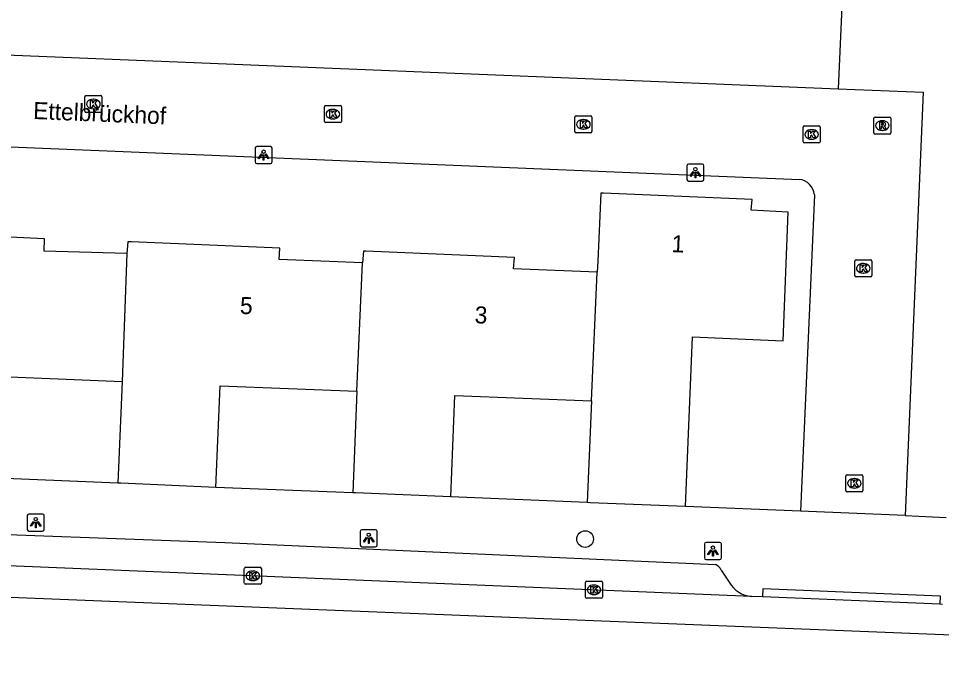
# Model space of a CAD drawing. Extents: x 160787 to 161428, y 386828 to 387483.
# Drawn here: x 161180.7 to 161234.9, y 386896.4 to 386934.4 of the extents above; entities that cross this region are included whole.
import ezdxf

# ---------------------------------------------------------------- set-up
doc = ezdxf.new("R2010")
doc.units = 0
for name, color, linetype in [('IMGEO_Boom', 7, 'Continuous'), ('IMGEO_Kolk', 7, 'Continuous'), ('IMGEO_Lichtpunt', 7, 'Continuous'), ('IMGEO_Openbare_ruimte_label', 7, 'Continuous'), ('IMGEO_Pand', 7, 'Continuous'), ('IMGEO_Pand_nummerreeks', 7, 'Continuous'), ('IMGEO_Rijbaan_lokaal_gesloten', 7, 'Continuous'), ('IMGEO_Rioolput', 7, 'Continuous'), ('IMGEO_Voetpad_open', 7, 'Continuous')]:
    doc.layers.add(name, color=color, linetype=linetype)

msp = doc.modelspace()

# ---------------------------------------------------------------- linework, layer by layer
at = {"layer": 'IMGEO_Boom'}
msp.add_circle((161213.924, 386903.837), 0.489, dxfattribs=at)
at = {"layer": 'IMGEO_Kolk'}
for p, q in [((161184.551, 386928.95), (161184.551, 386929.802)), ((161184.626, 386929.876), (161185.478, 386929.876)), ((161185.039, 386929.656), (161185.064, 386929.656)), ((161185.552, 386929.802), (161185.552, 386928.95)), ((161185.478, 386928.876), (161184.626, 386928.876)), ((161185.062, 386929.096), (161185.037, 386929.096)), ((161198.613, 386928.36), (161198.613, 386929.212)), ((161198.688, 386929.286), (161199.54, 386929.286)), ((161199.101, 386929.066), (161199.126, 386929.066)), ((161199.614, 386929.212), (161199.614, 386928.36)), ((161199.124, 386928.506), (161199.099, 386928.506)), ((161213.321, 386927.757), (161213.321, 386928.609)), ((161213.396, 386928.683), (161214.248, 386928.683)), ((161213.809, 386928.463), (161213.834, 386928.463)), ((161214.322, 386928.609), (161214.322, 386927.757)), ((161199.54, 386928.286), (161198.688, 386928.286)), ((161213.832, 386927.903), (161213.807, 386927.903)), ((161226.721, 386927.167), (161226.721, 386928.019)), ((161226.796, 386928.093), (161227.648, 386928.093)), ((161227.209, 386927.873), (161227.234, 386927.873)), ((161227.722, 386928.019), (161227.722, 386927.167)), ((161214.248, 386927.683), (161213.396, 386927.683)), ((161227.232, 386927.313), (161227.207, 386927.313)), ((161227.648, 386927.093), (161226.796, 386927.093)), ((161229.829, 386920.236), (161230.681, 386920.236)), ((161229.754, 386919.31), (161229.754, 386920.162)), ((161230.242, 386920.016), (161230.267, 386920.016)), ((161230.755, 386920.162), (161230.755, 386919.31)), ((161230.681, 386919.236), (161229.829, 386919.236)), ((161230.265, 386919.456), (161230.24, 386919.456)), ((161229.23, 386906.685), (161229.23, 386907.537)), ((161229.305, 386907.611), (161230.157, 386907.611)), ((161229.718, 386907.391), (161229.743, 386907.391)), ((161230.231, 386907.537), (161230.231, 386906.685)), ((161229.741, 386906.831), (161229.716, 386906.831)), ((161230.157, 386906.611), (161229.305, 386906.611)), ((161193.912, 386901.255), (161193.912, 386902.107)), ((161193.987, 386902.181), (161194.839, 386902.181)), ((161194.4, 386901.961), (161194.425, 386901.961)), ((161194.913, 386902.107), (161194.913, 386901.255)), ((161194.423, 386901.401), (161194.398, 386901.401)), ((161213.944, 386900.433), (161213.944, 386901.285)), ((161214.019, 386901.359), (161214.871, 386901.359)), ((161214.945, 386901.285), (161214.945, 386900.433)), ((161194.839, 386901.181), (161193.987, 386901.181)), ((161214.432, 386901.139), (161214.457, 386901.139)), ((161214.871, 386900.359), (161214.019, 386900.359)), ((161214.455, 386900.579), (161214.43, 386900.579))]:
    msp.add_line(p, q, dxfattribs=at)
for points in [[(161184.551, 386928.95), (161184.551, 386929.802)], [(161184.626, 386929.876), (161185.478, 386929.876)], [(161184.872, 386929.576), (161184.995, 386929.576), (161184.995, 386929.425), (161185.125, 386929.576), (161185.289, 386929.576), (161185.143, 386929.425), (161185.296, 386929.176), (161185.144, 386929.176), (161185.059, 386929.34), (161184.995, 386929.273), (161184.995, 386929.176), (161184.872, 386929.176), (161184.872, 386929.576)], [(161185.552, 386929.802), (161185.552, 386928.95)], [(161185.478, 386928.876), (161184.626, 386928.876)], [(161198.613, 386928.36), (161198.613, 386929.212)], [(161198.688, 386929.286), (161199.54, 386929.286)], [(161198.934, 386928.986), (161199.057, 386928.986), (161199.057, 386928.835), (161199.187, 386928.986), (161199.351, 386928.986), (161199.205, 386928.835), (161199.358, 386928.586), (161199.206, 386928.586), (161199.121, 386928.75), (161199.057, 386928.683), (161199.057, 386928.586), (161198.934, 386928.586), (161198.934, 386928.986)], [(161199.614, 386929.212), (161199.614, 386928.36)], [(161213.321, 386927.757), (161213.321, 386928.609)], [(161213.396, 386928.683), (161214.248, 386928.683)], [(161213.642, 386928.383), (161213.765, 386928.383), (161213.765, 386928.232), (161213.895, 386928.383), (161214.059, 386928.383), (161213.913, 386928.232), (161214.066, 386927.983), (161213.914, 386927.983), (161213.829, 386928.147), (161213.765, 386928.08), (161213.765, 386927.983), (161213.642, 386927.983), (161213.642, 386928.383)], [(161214.322, 386928.609), (161214.322, 386927.757)], [(161199.54, 386928.286), (161198.688, 386928.286)], [(161226.721, 386927.167), (161226.721, 386928.019)], [(161226.796, 386928.093), (161227.648, 386928.093)], [(161227.042, 386927.793), (161227.165, 386927.793), (161227.165, 386927.642), (161227.295, 386927.793), (161227.459, 386927.793), (161227.313, 386927.642), (161227.466, 386927.393), (161227.314, 386927.393), (161227.229, 386927.557), (161227.165, 386927.49), (161227.165, 386927.393), (161227.042, 386927.393), (161227.042, 386927.793)], [(161227.722, 386928.019), (161227.722, 386927.167)], [(161214.248, 386927.683), (161213.396, 386927.683)], [(161227.648, 386927.093), (161226.796, 386927.093)], [(161229.829, 386920.236), (161230.681, 386920.236)], [(161229.754, 386919.31), (161229.754, 386920.162)], [(161230.075, 386919.936), (161230.198, 386919.936), (161230.198, 386919.785), (161230.328, 386919.936), (161230.492, 386919.936), (161230.346, 386919.785), (161230.499, 386919.536), (161230.347, 386919.536), (161230.262, 386919.7), (161230.198, 386919.633), (161230.198, 386919.536), (161230.075, 386919.536), (161230.075, 386919.936)], [(161230.755, 386920.162), (161230.755, 386919.31)], [(161230.681, 386919.236), (161229.829, 386919.236)], [(161229.23, 386906.685), (161229.23, 386907.537)], [(161229.305, 386907.611), (161230.157, 386907.611)], [(161229.551, 386907.311), (161229.674, 386907.311), (161229.674, 386907.16), (161229.804, 386907.311), (161229.968, 386907.311), (161229.822, 386907.16), (161229.975, 386906.911), (161229.823, 386906.911), (161229.738, 386907.075), (161229.674, 386907.008), (161229.674, 386906.911), (161229.551, 386906.911), (161229.551, 386907.311)], [(161230.231, 386907.537), (161230.231, 386906.685)], [(161230.157, 386906.611), (161229.305, 386906.611)], [(161193.912, 386901.255), (161193.912, 386902.107)], [(161193.987, 386902.181), (161194.839, 386902.181)], [(161194.233, 386901.881), (161194.356, 386901.881), (161194.356, 386901.73), (161194.486, 386901.881), (161194.65, 386901.881), (161194.504, 386901.73), (161194.657, 386901.481), (161194.505, 386901.481), (161194.42, 386901.645), (161194.356, 386901.578), (161194.356, 386901.481), (161194.233, 386901.481), (161194.233, 386901.881)], [(161194.913, 386902.107), (161194.913, 386901.255)], [(161213.944, 386900.433), (161213.944, 386901.285)], [(161214.019, 386901.359), (161214.871, 386901.359)], [(161214.945, 386901.285), (161214.945, 386900.433)], [(161194.839, 386901.181), (161193.987, 386901.181)], [(161214.265, 386901.059), (161214.388, 386901.059), (161214.388, 386900.908), (161214.518, 386901.059), (161214.682, 386901.059), (161214.536, 386900.908), (161214.689, 386900.659), (161214.537, 386900.659), (161214.452, 386900.823), (161214.388, 386900.756), (161214.388, 386900.659), (161214.265, 386900.659), (161214.265, 386901.059)], [(161214.871, 386900.359), (161214.019, 386900.359)]]:
    msp.add_lwpolyline(points, dxfattribs=at)
for centre, start, end in [((161184.628, 386929.8), 91.552, 178.448), ((161184.628, 386929.8), 91.552, 178.448), ((161185.476, 386929.8), 1.552, 88.448), ((161185.476, 386929.8), 1.552, 88.448), ((161184.628, 386928.952), 181.552, 268.448), ((161184.628, 386928.952), 181.552, 268.448), ((161185.476, 386928.952), 271.552, 358.448), ((161185.476, 386928.952), 271.552, 358.448), ((161198.69, 386929.21), 91.552, 178.448), ((161198.69, 386929.21), 91.552, 178.448), ((161199.538, 386929.21), 1.552, 88.448), ((161199.538, 386929.21), 1.552, 88.448), ((161198.69, 386928.362), 181.552, 268.448), ((161198.69, 386928.362), 181.552, 268.448), ((161199.538, 386928.362), 271.552, 358.448), ((161199.538, 386928.362), 271.552, 358.448), ((161213.398, 386928.607), 91.552, 178.448), ((161213.398, 386928.607), 91.552, 178.448), ((161214.246, 386928.607), 1.552, 88.448), ((161214.246, 386928.607), 1.552, 88.448), ((161226.798, 386928.017), 91.552, 178.448), ((161226.798, 386928.017), 91.552, 178.448), ((161227.646, 386928.017), 1.552, 88.448), ((161227.646, 386928.017), 1.552, 88.448), ((161213.398, 386927.759), 181.552, 268.448), ((161213.398, 386927.759), 181.552, 268.448), ((161214.246, 386927.759), 271.552, 358.448), ((161214.246, 386927.759), 271.552, 358.448), ((161226.798, 386927.169), 181.552, 268.448), ((161226.798, 386927.169), 181.552, 268.448), ((161227.646, 386927.169), 271.552, 358.448), ((161227.646, 386927.169), 271.552, 358.448), ((161229.831, 386920.16), 91.552, 178.448), ((161229.831, 386920.16), 91.552, 178.448), ((161230.679, 386920.16), 1.552, 88.448), ((161230.679, 386920.16), 1.552, 88.448), ((161229.831, 386919.312), 181.552, 268.448), ((161229.831, 386919.312), 181.552, 268.448), ((161230.679, 386919.312), 271.552, 358.448), ((161230.679, 386919.312), 271.552, 358.448), ((161229.307, 386907.535), 91.552, 178.448), ((161229.307, 386907.535), 91.552, 178.448), ((161230.155, 386907.535), 1.552, 88.448), ((161230.155, 386907.535), 1.552, 88.448), ((161229.307, 386906.687), 181.552, 268.448), ((161229.307, 386906.687), 181.552, 268.448), ((161230.155, 386906.687), 271.552, 358.448), ((161230.155, 386906.687), 271.552, 358.448), ((161193.989, 386902.105), 91.552, 178.448), ((161193.989, 386902.105), 91.552, 178.448), ((161194.837, 386902.105), 1.552, 88.448), ((161194.837, 386902.105), 1.552, 88.448), ((161193.989, 386901.257), 181.552, 268.448), ((161193.989, 386901.257), 181.552, 268.448), ((161194.837, 386901.257), 271.552, 358.448), ((161194.837, 386901.257), 271.552, 358.448), ((161214.021, 386901.283), 91.552, 178.448), ((161214.021, 386901.283), 91.552, 178.448), ((161214.869, 386901.283), 1.552, 88.448), ((161214.869, 386901.283), 1.552, 88.448), ((161214.021, 386900.435), 181.552, 268.448), ((161214.021, 386900.435), 181.552, 268.448), ((161214.869, 386900.435), 271.552, 358.448), ((161214.869, 386900.435), 271.552, 358.448)]:
    msp.add_arc(centre, 0.0765, start, end, dxfattribs=at)
for centre, major_axis, ratio, start_param, end_param in [((161185.038, 386929.376), (-0.387, 0.002), 0.722429, 4.712389, 7.853982), ((161185.063, 386929.376), (-0.39, 0.002), 0.717154, 1.570796, 4.712389), ((161199.1, 386928.786), (-0.387, 0.002), 0.722429, 4.712389, 7.853982), ((161199.125, 386928.786), (-0.39, 0.002), 0.717154, 1.570796, 4.712389), ((161213.808, 386928.183), (-0.387, 0.002), 0.722429, 4.712389, 7.853982), ((161213.833, 386928.183), (-0.39, 0.002), 0.717154, 1.570796, 4.712389), ((161227.208, 386927.593), (-0.387, 0.002), 0.722429, 4.712389, 7.853982), ((161227.233, 386927.593), (-0.39, 0.002), 0.717154, 1.570796, 4.712389), ((161230.241, 386919.736), (-0.387, 0.002), 0.722429, 4.712389, 7.853982), ((161230.266, 386919.736), (-0.39, 0.002), 0.717154, 1.570796, 4.712389), ((161229.717, 386907.111), (-0.387, 0.002), 0.722429, 4.712389, 7.853982), ((161229.742, 386907.111), (-0.39, 0.002), 0.717154, 1.570796, 4.712389), ((161194.399, 386901.681), (-0.387, 0.002), 0.722429, 4.712389, 7.853982), ((161194.424, 386901.681), (-0.39, 0.002), 0.717154, 1.570796, 4.712389), ((161214.431, 386900.859), (-0.387, 0.002), 0.722429, 4.712389, 7.853982), ((161214.456, 386900.859), (-0.39, 0.002), 0.717154, 1.570796, 4.712389)]:
    msp.add_ellipse(centre, major_axis=major_axis, ratio=ratio, start_param=start_param, end_param=end_param, dxfattribs=at)
at = {"layer": 'IMGEO_Lichtpunt'}
for p, q in [((161194.543, 386926.783), (161194.543, 386925.976)), ((161194.543, 386926.783), (161194.543, 386925.976)), ((161195.445, 386926.878), (161194.637, 386926.878)), ((161195.445, 386926.878), (161194.637, 386926.878)), ((161195.539, 386925.976), (161195.539, 386926.783)), ((161195.539, 386925.976), (161195.539, 386926.783)), ((161194.637, 386925.882), (161195.445, 386925.882)), ((161194.637, 386925.882), (161195.445, 386925.882)), ((161219.9, 386925.757), (161219.9, 386924.95)), ((161219.9, 386925.757), (161219.9, 386924.95)), ((161220.802, 386925.852), (161219.994, 386925.852)), ((161220.802, 386925.852), (161219.994, 386925.852)), ((161220.896, 386924.95), (161220.896, 386925.757)), ((161220.896, 386924.95), (161220.896, 386925.757)), ((161219.994, 386924.856), (161220.802, 386924.856)), ((161219.994, 386924.856), (161220.802, 386924.856)), ((161181.167, 386905.212), (161181.167, 386904.405)), ((161181.167, 386905.212), (161181.167, 386904.405)), ((161182.069, 386905.307), (161181.261, 386905.307)), ((161182.069, 386905.307), (161181.261, 386905.307)), ((161182.163, 386904.405), (161182.163, 386905.212)), ((161182.163, 386904.405), (161182.163, 386905.212)), ((161181.261, 386904.311), (161182.069, 386904.311)), ((161181.261, 386904.311), (161182.069, 386904.311)), ((161200.719, 386904.291), (161200.719, 386903.484)), ((161200.719, 386904.291), (161200.719, 386903.484)), ((161201.621, 386904.386), (161200.813, 386904.386)), ((161201.621, 386904.386), (161200.813, 386904.386)), ((161201.715, 386903.484), (161201.715, 386904.291)), ((161201.715, 386903.484), (161201.715, 386904.291)), ((161220.93, 386903.54), (161220.93, 386902.733)), ((161220.93, 386903.54), (161220.93, 386902.733)), ((161221.832, 386903.635), (161221.024, 386903.635)), ((161221.832, 386903.635), (161221.024, 386903.635)), ((161221.926, 386902.733), (161221.926, 386903.54)), ((161221.926, 386902.733), (161221.926, 386903.54)), ((161200.813, 386903.39), (161201.621, 386903.39)), ((161200.813, 386903.39), (161201.621, 386903.39)), ((161221.024, 386902.639), (161221.832, 386902.639)), ((161221.024, 386902.639), (161221.832, 386902.639))]:
    msp.add_line(p, q, dxfattribs=at)
for points in [[(161194.917, 386926.447), (161194.956, 386926.419), (161194.768, 386926.157), (161194.73, 386926.184), (161194.917, 386926.447)], [(161195.019, 386926.399), (161195.066, 386926.399), (161195.066, 386926.077), (161195.019, 386926.077), (161195.019, 386926.399)], [(161195.129, 386926.419), (161195.167, 386926.446), (161195.354, 386926.184), (161195.315, 386926.156), (161195.129, 386926.419)], [(161220.274, 386925.421), (161220.313, 386925.393), (161220.125, 386925.131), (161220.087, 386925.158), (161220.274, 386925.421)], [(161220.376, 386925.373), (161220.423, 386925.373), (161220.423, 386925.051), (161220.376, 386925.051), (161220.376, 386925.373)], [(161220.486, 386925.393), (161220.524, 386925.42), (161220.711, 386925.158), (161220.672, 386925.13), (161220.486, 386925.393)], [(161181.541, 386904.876), (161181.58, 386904.848), (161181.392, 386904.586), (161181.354, 386904.613), (161181.541, 386904.876)], [(161181.643, 386904.828), (161181.69, 386904.828), (161181.69, 386904.506), (161181.643, 386904.506), (161181.643, 386904.828)], [(161181.753, 386904.848), (161181.791, 386904.875), (161181.978, 386904.613), (161181.939, 386904.585), (161181.753, 386904.848)], [(161201.093, 386903.955), (161201.132, 386903.927), (161200.944, 386903.665), (161200.906, 386903.692), (161201.093, 386903.955)], [(161201.305, 386903.927), (161201.343, 386903.954), (161201.53, 386903.692), (161201.491, 386903.664), (161201.305, 386903.927)], [(161201.195, 386903.907), (161201.242, 386903.907), (161201.242, 386903.585), (161201.195, 386903.585), (161201.195, 386903.907)], [(161221.304, 386903.204), (161221.343, 386903.176), (161221.155, 386902.914), (161221.117, 386902.941), (161221.304, 386903.204)], [(161221.406, 386903.156), (161221.453, 386903.156), (161221.453, 386902.834), (161221.406, 386902.834), (161221.406, 386903.156)], [(161221.516, 386903.176), (161221.554, 386903.203), (161221.741, 386902.941), (161221.702, 386902.913), (161221.516, 386903.176)]]:
    msp.add_lwpolyline(points, dxfattribs=at)
for centre in [(161195.042, 386926.581), (161220.399, 386925.555), (161181.666, 386905.01), (161201.218, 386904.089), (161221.429, 386903.338)]:
    msp.add_circle(centre, 0.0994, dxfattribs=at)
for centre, start, end in [((161194.637, 386926.783), 90, 180), ((161194.637, 386926.783), 90, 180), ((161195.445, 386926.783), 0, 90), ((161195.445, 386926.783), 0, 90), ((161194.637, 386925.976), 180, 270), ((161194.637, 386925.976), 180, 270), ((161195.445, 386925.976), 270, 0), ((161195.445, 386925.976), 270, 360), ((161219.994, 386925.757), 90, 180), ((161219.994, 386925.757), 90, 180), ((161220.802, 386925.757), 0, 90), ((161220.802, 386925.757), 0, 90), ((161219.994, 386924.95), 180, 270), ((161219.994, 386924.95), 180, 270), ((161220.802, 386924.95), 270, 0), ((161220.802, 386924.95), 270, 360), ((161181.261, 386905.212), 90, 180), ((161181.261, 386905.212), 90, 180), ((161182.069, 386905.212), 0, 90), ((161182.069, 386905.212), 0, 90), ((161181.261, 386904.405), 180, 270), ((161181.261, 386904.405), 180, 270), ((161182.069, 386904.405), 270, 0), ((161182.069, 386904.405), 270, 360), ((161200.813, 386904.291), 90, 180), ((161200.813, 386904.291), 90, 180), ((161201.621, 386904.291), 0, 90), ((161201.621, 386904.291), 0, 90), ((161200.813, 386903.484), 180, 270), ((161200.813, 386903.484), 180, 270), ((161201.621, 386903.484), 270, 0), ((161201.621, 386903.484), 270, 360), ((161221.024, 386903.54), 90, 180), ((161221.024, 386903.54), 90, 180), ((161221.832, 386903.54), 0, 90), ((161221.832, 386903.54), 0, 90), ((161221.024, 386902.733), 180, 270), ((161221.024, 386902.733), 180, 270), ((161221.832, 386902.733), 270, 0), ((161221.832, 386902.733), 270, 360)]:
    msp.add_arc(centre, 0.0946, start, end, dxfattribs=at)
at = {"layer": 'IMGEO_Pand'}
for points in [[(161219.809, 386905.751), (161220.23, 386915.714), (161225.555, 386915.471), (161225.845, 386923.021), (161223.681, 386923.138), (161223.723, 386923.769), (161215.008, 386924.139), (161214.838, 386924.146), (161214.661, 386920.153), (161214.632, 386919.507)], [(161187.022, 386920.605), (161182.164, 386920.731), (161182.182, 386921.468), (161173.621, 386921.87)], [(161200.842, 386920.057), (161195.966, 386920.25), (161195.994, 386920.907), (161187.278, 386921.281), (161187.08, 386921.289), (161187.022, 386920.605)], [(161187.022, 386920.605), (161186.74, 386913.083)], [(161214.632, 386919.507), (161209.716, 386919.702), (161209.772, 386920.362), (161201.052, 386920.733), (161200.909, 386920.739), (161200.842, 386920.057)], [(161200.523, 386912.522), (161200.842, 386920.057)], [(161214.292, 386911.946), (161214.632, 386919.507)], [(161178.458, 386907.447), (161178.706, 386913.412), (161186.74, 386913.083)], [(161186.74, 386913.083), (161186.492, 386907.118)], [(161192.24, 386906.863), (161192.488, 386912.828), (161200.523, 386912.522)], [(161200.523, 386912.522), (161200.275, 386906.557)], [(161206.033, 386906.311), (161206.281, 386912.276), (161214.292, 386911.946)], [(161214.292, 386911.946), (161214.044, 386905.981)], [(161192.24, 386906.863), (161186.669, 386907.11), (161186.492, 386907.118)], [(161206.033, 386906.311), (161200.447, 386906.55), (161200.275, 386906.557)], [(161219.809, 386905.751), (161214.226, 386905.974), (161214.044, 386905.981)]]:
    msp.add_lwpolyline(points, dxfattribs=at)
at = {"layer": 'IMGEO_Rijbaan_lokaal_gesloten'}
for points in [[(161223.699, 386900.466), (161162.46, 386902.982)], [(161280.349, 386896.413), (161248.174, 386897.682), (161123.39, 386902.685)], [(161224.348, 386900.439), (161223.699, 386900.466)], [(161234.751, 386900.009), (161224.348, 386900.439)], [(161234.905, 386900.003), (161234.751, 386900.009)]]:
    msp.add_lwpolyline(points, dxfattribs=at)
at = {"layer": 'IMGEO_Rioolput'}
for p, q in [((161230.873, 386927.687), (161230.873, 386928.539)), ((161230.948, 386928.613), (161231.8, 386928.613)), ((161231.361, 386928.393), (161231.386, 386928.393)), ((161231.874, 386928.539), (161231.874, 386927.687)), ((161231.384, 386927.833), (161231.359, 386927.833)), ((161231.8, 386927.613), (161230.948, 386927.613))]:
    msp.add_line(p, q, dxfattribs=at)
for points in [[(161230.873, 386927.687), (161230.873, 386928.539)], [(161230.948, 386928.613), (161231.8, 386928.613)], [(161231.874, 386928.539), (161231.874, 386927.687)], [(161231.462, 386928.311), (161231.21, 386928.313), (161231.21, 386927.913)], [(161231.21, 386927.913), (161231.334, 386927.913), (161231.334, 386928.075), (161231.345, 386928.075)], [(161231.388, 386928.232), (161231.334, 386928.232), (161231.334, 386928.151)], [(161231.334, 386928.151), (161231.386, 386928.151)], [(161231.392, 386928.046), (161231.463, 386927.913), (161231.603, 386927.913), (161231.538, 386928.039)], [(161231.8, 386927.613), (161230.948, 386927.613)]]:
    msp.add_lwpolyline(points, dxfattribs=at)
for centre, radius, start, end in [((161230.95, 386928.537), 0.0765, 91.552, 178.448), ((161230.95, 386928.537), 0.0765, 91.552, 178.448), ((161231.798, 386928.537), 0.0765, 1.552, 88.448), ((161231.798, 386928.537), 0.0765, 1.552, 88.448), ((161231.344, 386928.022), 0.0533, 26.0293, 88.6989), ((161231.37, 386928.34), 0.19, 274.7715, 282.9687), ((161231.394, 386928.136), 0.0964, 77.0061, 93.1865), ((161231.408, 386928.193), 0.0378, 276.6634, 79.6772), ((161231.461, 386928.201), 0.109, 350.3612, 89.416), ((161231.459, 386928.201), 0.112, 277.5842, 350.9817), ((161231.443, 386927.986), 0.108, 29.5134, 73.7905), ((161230.95, 386927.689), 0.0765, 181.552, 268.448), ((161230.95, 386927.689), 0.0765, 181.552, 268.448), ((161231.798, 386927.689), 0.0765, 271.552, 358.448), ((161231.798, 386927.689), 0.0765, 271.552, 358.448)]:
    msp.add_arc(centre, radius, start, end, dxfattribs=at)
for centre, major_axis, ratio, start_param, end_param in [((161231.36, 386928.113), (-0.387, 0.002), 0.722429, 4.712389, 7.853982), ((161231.385, 386928.113), (-0.39, 0.002), 0.717154, 1.570796, 4.712389)]:
    msp.add_ellipse(centre, major_axis=major_axis, ratio=ratio, start_param=start_param, end_param=end_param, dxfattribs=at)
at = {"layer": 'IMGEO_Voetpad_open'}
for points in [[(161229.023, 386935.547), (161228.777, 386930.274)], [(161159.797, 386933.081), (161228.777, 386930.274)], [(161228.777, 386930.274), (161233.768, 386930.072), (161232.717, 386905.215)], [(161162.187, 386927.617), (161226.501, 386924.954)], [(161227.385, 386924.042), (161226.578, 386905.472)], [(161186.492, 386907.118), (161178.458, 386907.447)], [(161200.275, 386906.557), (161192.24, 386906.863)], [(161214.044, 386905.981), (161206.033, 386906.311)], [(161226.578, 386905.472), (161219.809, 386905.751)], [(161232.717, 386905.215), (161226.578, 386905.472)], [(161232.717, 386905.215), (161235.128, 386905.104)], [(161165.97, 386904.699), (161174.681, 386904.304), (161192.762, 386903.644), (161221.57, 386902.335)], [(161221.913, 386902.02), (161222.38, 386901.304)], [(161224.348, 386900.439), (161224.368, 386900.938), (161234.771, 386900.508), (161234.751, 386900.009)]]:
    msp.add_lwpolyline(points, dxfattribs=at)
for centre, radius, start, end in [((161226.387, 386923.959), 1.002, 4.7668, 83.4468), ((161221.325, 386901.724), 0.659, 26.7295, 68.1438), ((161223.863, 386902.182), 1.724, 210.6168, 264.5252)]:
    msp.add_arc(centre, radius, start, end, dxfattribs=at)

# ---------------------------------------------------------------- texts
at = {"layer": 'IMGEO_Openbare_ruimte_label'}
msp.add_text('Ettelbrückhof', height=1, rotation=357.6498, dxfattribs=at).set_placement((161181.499, 386928.502))
at = {"layer": 'IMGEO_Pand_nummerreeks'}
for s, rotation, p in [('1', 357.5703, (161218.981, 386920.687)), ('5', 357.7333, (161193.641, 386917.059)), ('3', 357.7285, (161207.422, 386916.51))]:
    msp.add_text(s, height=1, rotation=rotation, dxfattribs=at).set_placement(p)

doc.saveas('drawing.dxf')
